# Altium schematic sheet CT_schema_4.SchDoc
size 287 x 160 mm
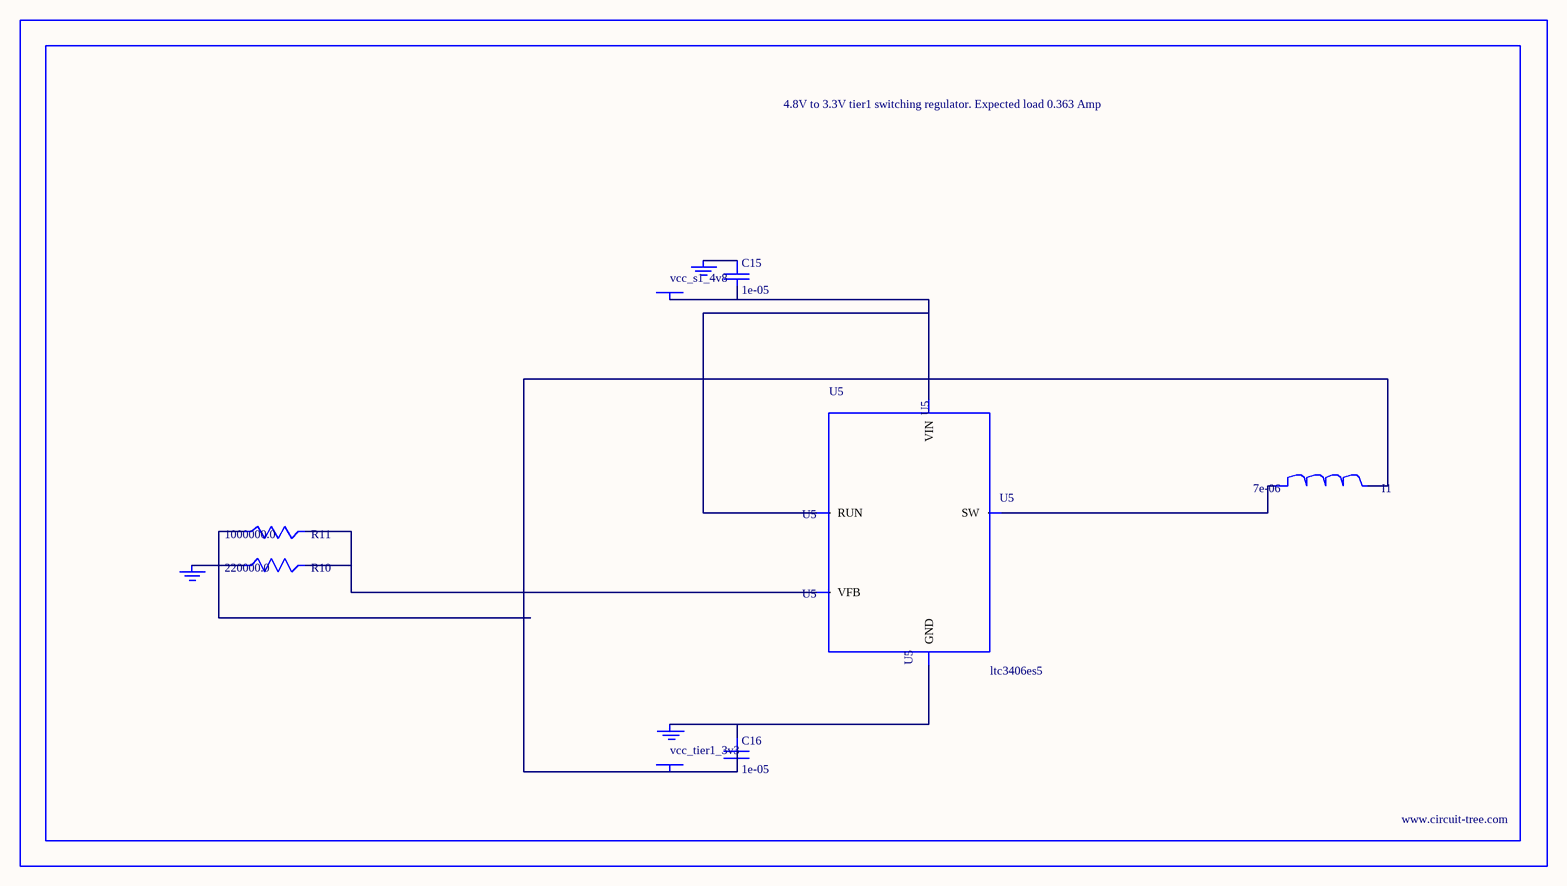
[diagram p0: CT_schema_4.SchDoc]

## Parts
BORDER3  (no value)
C15  1e-05  [C0805]
C16  1e-05  [C0805]
GND_INSTANCE_3_0  (no value)
GND_INSTANCE_3_1  (no value)
GND_INSTANCE_3_2  (no value)
I1  7e-06  [DR1040]
POWER_INSTANCE_3_0  vcc_tier1_3v3
POWER_INSTANCE_3_1  vcc_s1_4v8
R10  220000.0  [R0603]
R11  1000000.0  [R0603]
U5  ltc3406es5  [TSOT-23-5]

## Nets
NetC15_1: C15.1 GND_INSTANCE_3_1.0(GND)
NetC15_2: C15.2 POWER_INSTANCE_3_1.0(PWR) U5.1(RUN) U5.4(VIN)
NetC16_1: C16.1 GND_INSTANCE_3_0.0(GND) U5.2(GND)
NetC16_2: C16.2 I1.2 POWER_INSTANCE_3_0.0(PWR) R11.1
NetGND_INSTANCE_3_2_0: GND_INSTANCE_3_2.0(GND) R10.1
NetI1_1: I1.1 U5.3(SW)
NetR10_2: R10.2 R11.2 U5.5(VFB)

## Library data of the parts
BORDER3 = BORDER_PAGE3
C15 C16 = C0805C106K8RACTU
GND_INSTANCE_3_0-GND_INSTANCE_3_2 = GND
I1 = DR1040-7R0-R
POWER_INSTANCE_3_0 POWER_INSTANCE_3_1 = PWR
R10 = RC0603JR-07220KL
R11 = RC0603JR-071ML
